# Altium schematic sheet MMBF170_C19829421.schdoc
size 127 x 101 mm
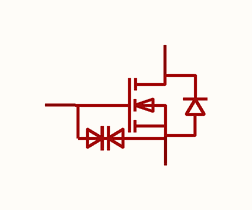
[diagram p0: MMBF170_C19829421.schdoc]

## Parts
Q?  mmbf170_c19829421  [SOT-23-3_L2.9-W1.4-P1.90-LS2.5-BR]  (value not drawn)

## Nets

Not connected (* = marked no-connect by the designer): Q? 1(G) 2(S) 3(D)

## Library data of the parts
Q? = mmbf170_c19829421: 漏源电压(Vdss):60V;连续漏极电流(Id):300mA;导通电阻(RDS(on)):2.2Ω@10V,0.3A;耗散功率(Pd):350mW;阈值电压(Vgs(th)):1.6V;; Manufacturer: TECH PUBLIC(台舟); AddInBom: yes; ModelId: 9c0df02d6f3e44e889da37f3e5bf5496; ModelTransform: 98.425,114.173,0,0,0,0,0,0,0; Drain to Source Voltage: 60V; Current - Continuous Drain(Id): 300mA; Pd - Power Dissipation: 350mW; Gate Threshold Voltage (Vgs(th)@Id): 1.6V; Gate Charge(Qg): 3nC@4.5V; Input Capacitance(Ciss@Vds): 27pF@30V; Reverse Transfer Capacitance (Crss@Vds): 2pF@30V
